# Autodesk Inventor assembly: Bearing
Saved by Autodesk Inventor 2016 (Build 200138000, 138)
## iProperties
Created: 2015-08
Part Number: Bearing
Document SubType Name: Assembly
Designer: stank
ClientObjectVersion: 1
Author: stank
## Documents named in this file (2)
- E:\Turbokompr\Sklop turbokompresora\Design Accelerator\Bearing3.iam
- C:\Users\stank\Documents\Inventor\Content Center Files\R2016\en-US\BS 292 (V)\BS 292_ Part 1 - N 1005 - 25 x 47 x 12.ipt
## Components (1 placed, 1 different names)
1. BS 292: Part 1 (V) (Metric) N 1005 - 25 x 47 x 12:1
